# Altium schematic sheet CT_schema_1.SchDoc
size 464 x 288 mm
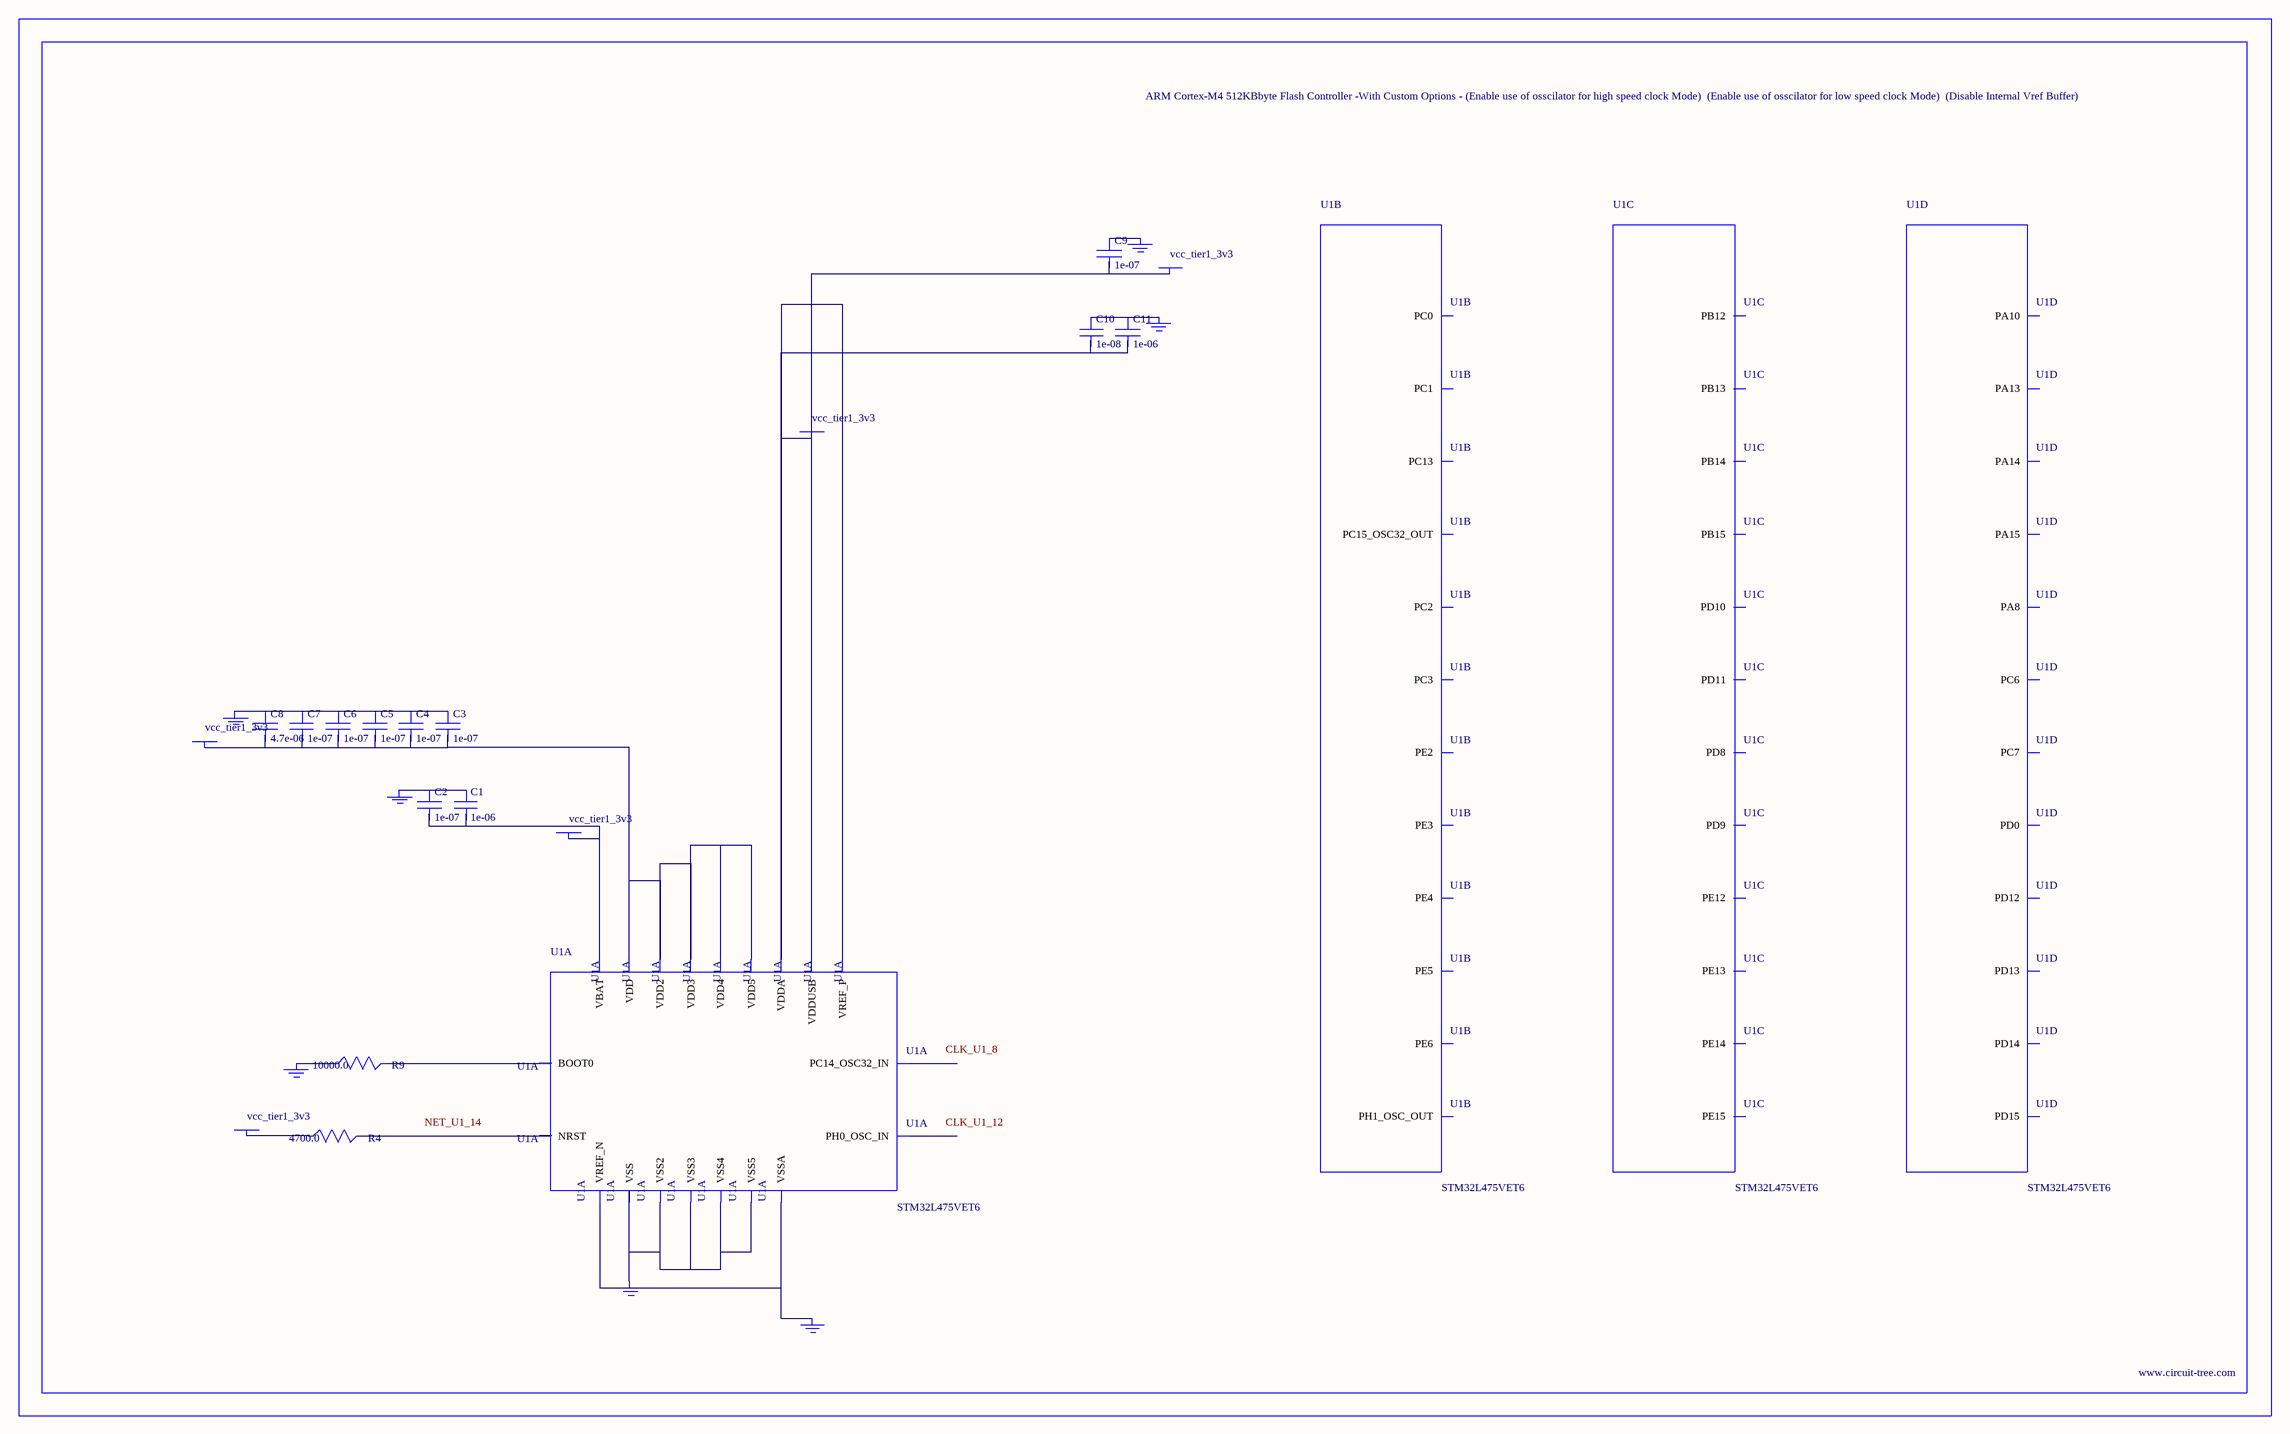
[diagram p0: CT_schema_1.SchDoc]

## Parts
BORDER0  (no value)
C1  1e-06  [C0603]
C2  1e-07  [C0603]
C3  1e-07  [C0603]
C4  1e-07  [C0603]
C5  1e-07  [C0603]
C6  1e-07  [C0603]
C7  1e-07  [C0603]
C8  4.7e-06  [C0603]
C9  1e-07  [C0603]
C10  1e-08  [C0603]
C11  1e-06  [C0603]
GND_INSTANCE_0_0  (no value)
GND_INSTANCE_0_1  (no value)
GND_INSTANCE_0_2  (no value)
GND_INSTANCE_0_3  (no value)
GND_INSTANCE_0_4  (no value)
GND_INSTANCE_0_5  (no value)
GND_INSTANCE_0_6  (no value)
POWER_INSTANCE_0_0  vcc_tier1_3v3
POWER_INSTANCE_0_1  vcc_tier1_3v3
POWER_INSTANCE_0_2  vcc_tier1_3v3
POWER_INSTANCE_0_3  vcc_tier1_3v3
POWER_INSTANCE_0_4  vcc_tier1_3v3
R4  4700.0  [R0603]
R9  10000.0  [R0603]
U1  STM32L475VET6  [LQFP100]  (parts A,B,C,D of 9)

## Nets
NetC1_1: C1.1 C2.1 GND_INSTANCE_0_0.0(GND)
NetC1_2: C1.2 C2.2 POWER_INSTANCE_0_0.0(PWR) U1.6(VBAT)
NetC3_1: C3.1 C4.1 C5.1 C6.1 C7.1 C8.1 GND_INSTANCE_0_1.0(GND)
NetC3_2: C3.2 C4.2 C5.2 C6.2 C7.2 C8.2 POWER_INSTANCE_0_1.0(PWR) U1.11(VDD) U1.28(VDD2) U1.50(VDD3) U1.75(VDD4) U1.100(VDD5)
NetC9_1: C9.1 GND_INSTANCE_0_4.0(GND)
NetC9_2: C9.2 C10.2 C11.2 POWER_INSTANCE_0_2.0(PWR) POWER_INSTANCE_0_3.0(PWR) U1.21(VREF_P) U1.22(VDDA) U1.73(VDDUSB)
NetC10_1: C10.1 C11.1 GND_INSTANCE_0_3.0(GND)
NetGND_INSTANCE_0_2_0: GND_INSTANCE_0_2.0(GND) U1.19(VSSA) U1.20(VREF_N)
NetGND_INSTANCE_0_5_0: GND_INSTANCE_0_5.0(GND) R9.1
NetGND_INSTANCE_0_6_0: GND_INSTANCE_0_6.0(GND) U1.10(VSS) U1.27(VSS2) U1.49(VSS3) U1.74(VSS4) U1.99(VSS5)
NetPOWER_INSTANCE_0_4_0: POWER_INSTANCE_0_4.0(PWR) R4.1
NetR4_2: R4.2 U1.14(NRST)
NetR9_2: R9.2 U1.94(BOOT0)

Not connected (* = marked no-connect by the designer): U1 1(PE2) 2(PE3) 3(PE4) 4(PE5) 5(PE6) 7(PC13) 8(PC14_OSC32_IN) 9(PC15_OSC32_OUT) 12(PH0_OSC_IN) 13(PH1_OSC_OUT) 15(PC0) 16(PC1) 17(PC2) 18(PC3) 43(PE12) 44(PE13) 45(PE14) 46(PE15) 51(PB12) 52(PB13) 53(PB14) 54(PB15) 55(PD8) 56(PD9) 57(PD10) 58(PD11) 59(PD12) 60(PD13) 61(PD14) 62(PD15) 63(PC6) 64(PC7) 67(PA8) 69(PA10) 72(PA13) 76(PA14) 77(PA15) 81(PD0)

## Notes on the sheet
- Labels drawn without touching a wire or pin: CLK_U1_8, CLK_U1_12, NET_U1_14

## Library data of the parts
BORDER0 = BORDER_PAGE0
C1 C11 = C0603C105K3RACTU
C2-C7 C9 = 06035C104K4Z2A
C8 = GRM188R6YA475KE15D
C10 = 06035C103K4Z2A
GND_INSTANCE_0_0-GND_INSTANCE_0_6 = GND
POWER_INSTANCE_0_0-POWER_INSTANCE_0_4 = PWR
R4 = RC0603JR-074K7L
R9 = RC0603JR-0710KL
